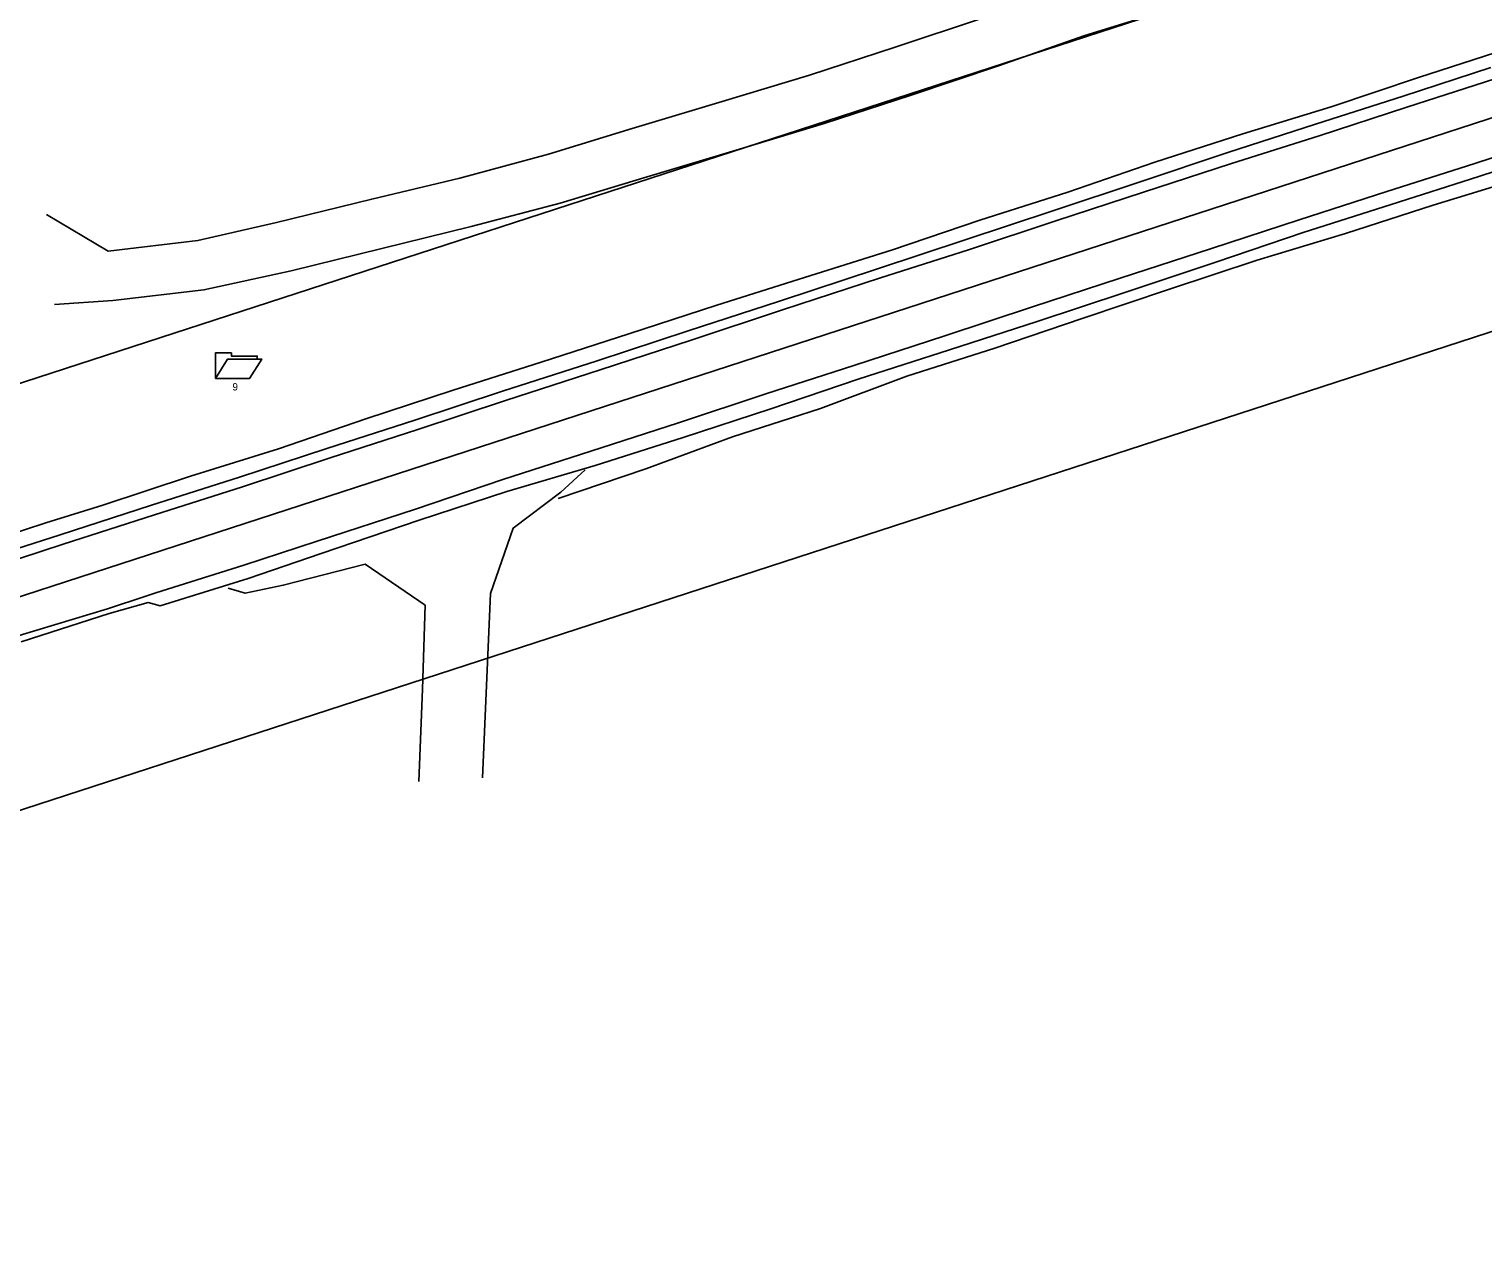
# Model space of a CAD drawing. Extents: x 1713040 to 1720428, y 375934 to 378258.
# Drawn here: x 1716759.2 to 1717153.3, y 376372.6 to 376701.3 of the extents above; entities that cross this region are included whole.
import ezdxf

# ---------------------------------------------------------------- set-up
doc = ezdxf.new("R2010")
doc.units = 0
for name, color, linetype in [('S_DRIVEWAY', 7, 'Continuous'), ('S_EDGE_PAVEMENT', 7, 'Continuous'), ('S_EXIST_ROW', 7, 'Continuous'), ('S_EXISTING_ALIGNMENT', 7, 'Continuous'), ('S_GRAVEL_ROAD', 7, 'Continuous'), ('S_SHOULDER', 7, 'Continuous'), ('S_TRAILS', 7, 'Continuous'), ('Scan Positions', 7, 'Continuous')]:
    doc.layers.add(name, color=color, linetype=linetype)

msp = doc.modelspace()

# ---------------------------------------------------------------- linework, layer by layer
at = {"layer": 'S_DRIVEWAY'}
for points in [[(1716882.16, 376498.38), (1716883.23, 376523.35), (1716884.3, 376548.31), (1716890.51, 376566.05), (1716903.39, 376575.78), (1716909.96, 376581.84)], [(1716864.93, 376497.4), (1716865.87, 376522.42), (1716866.58, 376545.15), (1716850.34, 376556.24), (1716828.15, 376550.57), (1716817.78, 376548.4), (1716813.19, 376549.8)]]:
    msp.add_lwpolyline(points, dxfattribs=at)
at = {"layer": 'S_EDGE_PAVEMENT'}
for points in [[(1716744.76, 376553.9), (1716768.53, 376561.65), (1716793.28, 376569.62), (1716817.1, 376577.21), (1716840.84, 376585.04), (1716864.62, 376592.74), (1716888.36, 376600.59), (1716914.03, 376608.97), (1716938.75, 376617), (1716963.44, 376625.16), (1716990.05, 376633.86), (1717013.85, 376641.49), (1717037.6, 376649.32), (1717061.36, 376657.07), (1717085.14, 376664.81), (1717108.96, 376672.38), (1717132.73, 376680.11), (1717156.52, 376687.8)], [(1716756.59, 376536.89), (1716780.52, 376544.16), (1716790.93, 376547.56), (1716793.63, 376548.46), (1716817.47, 376555.99), (1716837.38, 376562.48), (1716863.99, 376571.18), (1716887.68, 376579.17), (1716911.48, 376586.85), (1716935.25, 376594.58), (1716958.99, 376602.4), (1716982.78, 376610.12), (1717007.51, 376618.14), (1717031.26, 376625.97), (1717055.02, 376633.73), (1717079.73, 376641.83), (1717103.5, 376649.56), (1717127.3, 376657.25), (1717151.12, 376664.84), (1717174.88, 376672.63)]]:
    msp.add_lwpolyline(points, dxfattribs=at)
at = {"layer": 'S_EXIST_ROW'}
for p, q in [((1716721.79, 376593.89), (1719194.33, 377397.97)), ((1716721.79, 376593.89), (1719194.33, 377397.97)), ((1716397, 376372.59), (1719323.44, 377324.29)), ((1716397, 376372.59), (1719321.66, 377323.71))]:
    msp.add_line(p, q, dxfattribs=at)
at = {"layer": 'S_EXISTING_ALIGNMENT'}
msp.add_line((1716440.47, 376444.57), (1719554.59, 377457.3), dxfattribs=at)
at = {"layer": 'S_GRAVEL_ROAD'}
for points in [[(1716740.04, 376559.72), (1716763.83, 376567.47), (1716779.25, 376572.22), (1716803, 376580.1), (1716826.84, 376587.52), (1716850.52, 376595.61), (1716874.25, 376603.41), (1716898.1, 376611), (1716921.85, 376618.69), (1716945.64, 376626.41), (1716969.47, 376633.95), (1716993.29, 376641.49), (1717016.99, 376649.49), (1717040.8, 376657.1), (1717064.43, 376665.22), (1717088.28, 376672.85), (1717112.2, 376680.2), (1717135.87, 376688.14), (1717159.66, 376695.85)], [(1716902.64, 376574.07), (1716926.46, 376582.1), (1716949.96, 376590.81), (1716973.82, 376598.41), (1716997.17, 376607.23), (1717021.01, 376614.76), (1717044.72, 376622.81), (1717068.4, 376630.83), (1717092.14, 376638.69), (1717116.06, 376645.84), (1717139.84, 376653.51), (1717163.76, 376660.89)]]:
    msp.add_lwpolyline(points, dxfattribs=at)
at = {"layer": 'S_SHOULDER'}
for points in [[(1716743.88, 376556.61), (1716767.71, 376564.18), (1716792.43, 376572.22), (1716816.25, 376579.83), (1716839.99, 376587.64), (1716863.79, 376595.32), (1716887.54, 376603.12), (1716913.26, 376611.34), (1716937.95, 376619.47), (1716962.66, 376627.56), (1716989.26, 376636.3), (1717012.98, 376644.18), (1717036.72, 376652.03), (1717060.45, 376659.89), (1717084.16, 376667.83), (1717107.93, 376675.53), (1717131.75, 376683.11), (1717155.51, 376690.88)], [(1716757.15, 376535.17), (1716780.94, 376542.87), (1716791.49, 376545.83), (1716794.77, 376544.94), (1716818.64, 376552.38), (1716838.45, 376559.19), (1716864.98, 376568.15), (1716888.72, 376575.98), (1716912.72, 376583), (1716936.54, 376590.59), (1716960.29, 376598.4), (1716983.98, 376606.43), (1717008.74, 376614.35), (1717032.55, 376621.99), (1717056.27, 376629.88), (1717080.93, 376638.12), (1717104.63, 376646.1), (1717128.44, 376653.76), (1717152.27, 376661.32), (1717176.03, 376669.09)]]:
    msp.add_lwpolyline(points, dxfattribs=at)
at = {"layer": 'S_TRAILS'}
for points in [[(1716763.96, 376650.99), (1716780.71, 376641.1), (1716805.01, 376643.95), (1716826.29, 376648.84), (1716852.13, 376655.2), (1716876.05, 376660.89), (1716900.07, 376667.34), (1716922.7, 376674.3), (1716947.11, 376681.63), (1716970.82, 376688.76), (1716994.05, 376696.37), (1717017.71, 376704.19), (1717040.61, 376712.35), (1717066.34, 376720.24), (1717088.7, 376727.22), (1717112.41, 376735.02), (1717136.82, 376743.33), (1717159.07, 376751.54)], [(1716766.16, 376626.67), (1716781.92, 376627.69), (1716806.63, 376630.59), (1716830.3, 376635.78), (1716854.87, 376641.82), (1716879.07, 376647.73), (1716903.22, 376654.1), (1716926.81, 376661.22), (1716950.88, 376668.45), (1716974.73, 376675.72), (1716998.35, 376683.4), (1717022.05, 376691.29), (1717045.43, 376699.57), (1717069.82, 376707.04), (1717093.07, 376714.87), (1717116.92, 376722.39), (1717140.9, 376730.13), (1717164.03, 376738.7)]]:
    msp.add_lwpolyline(points, dxfattribs=at)
at = {"layer": 'Scan Positions'}
for points in [[(1716809.78, 376606.6), (1716809.78, 376613.52), (1716814.11, 376613.52), (1716814.11, 376612.63), (1716821.12, 376612.63), (1716821.12, 376611.82), (1716813.08, 376611.82)], [(1716809.78, 376606.6), (1716819.03, 376606.6), (1716822.32, 376611.82), (1716813.08, 376611.82)]]:
    msp.add_lwpolyline(points, close=True, dxfattribs=at)

# ---------------------------------------------------------------- texts
msp.add_text('9', height=2, dxfattribs=at).set_placement((1716814.38, 376603.33))

doc.saveas('drawing.dxf')
